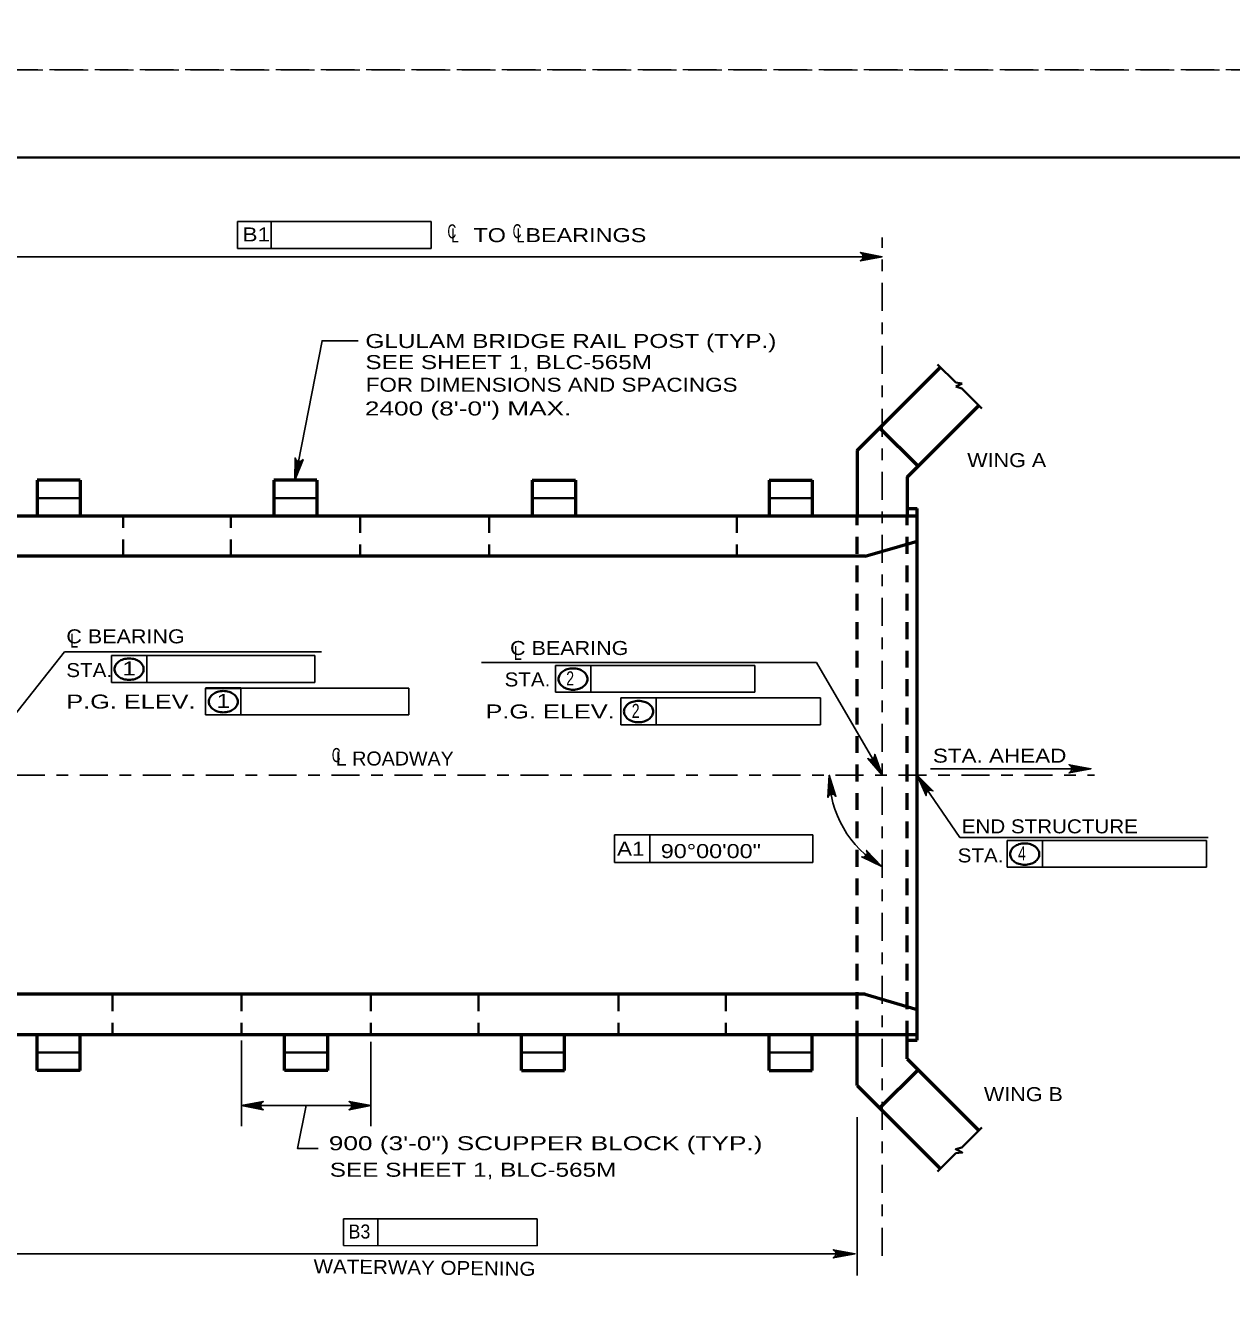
# Model space of a CAD drawing. Extents: x -11 to 79, y -154 to 0.
# Drawn here: x 5.96 to 16.3, y -32.54 to -21.62 of the extents above; entities that cross this region are included whole.
import ezdxf
from ezdxf.enums import TextEntityAlignment as Align

# ---------------------------------------------------------------- set-up
doc = ezdxf.new("R2010")
doc.units = 0
doc.header["$LTSCALE"] = 0.048
for name, pattern in [('DOT_DASHED', [7.7, 5, -1.2, 0.3, -1.2]), ('LONG_DASHED', [7.5, 6, -1.5]), ('MEDIUM_DASHED', [4.5, 3, -1.5])]:
    doc.linetypes.add(name, pattern=pattern)
for name, color, linetype, lineweight in [('1', 7, 'Continuous', 25), ('2', 7, 'Continuous', 35), ('3', 7, 'Continuous', 25), ('4', 7, 'Continuous', 25), ('63', 7, 'LONG_DASHED', 13)]:
    doc.layers.add(name, color=color, linetype=linetype, lineweight=lineweight)

msp = doc.modelspace()

# ---------------------------------------------------------------- hatches: boundary and pattern name
at = {"layer": '4'}
for points in [[(7.929, -30.85975), (7.929, -30.89917), (7.81083, -30.8795)], [(8.80092, -30.85975), (8.80092, -30.89917), (8.91908, -30.8795)]]:
    msp.add_hatch(color=256, dxfattribs=at).paths.add_polyline_path(points)

# ---------------------------------------------------------------- linework, layer by layer
at = {"layer": '1', "lineweight": 35}
msp.add_lwpolyline([(1.75, -43.25), (33.25, -43.25), (33.25, -22.75), (1.75, -22.75)], close=True, dxfattribs=at)
at = {"layer": '2', "lineweight": 53}
for p, q in [((13.08867, -25.26242), (13.80325, -24.54783)), ((13.61158, -25.398), (14.1325, -24.87708)), ((13.08867, -25.26242), (13.08867, -25.82425)), ((6.42675, -25.51667), (6.05767, -25.51667)), ((6.05767, -25.51667), (6.05767, -25.82425)), ((6.42675, -25.51667), (6.42675, -25.82425)), ((8.45675, -25.51667), (8.08767, -25.51667)), ((8.08767, -25.51667), (8.08767, -25.82425)), ((8.45675, -25.51667), (8.45675, -25.82425)), ((10.304, -25.51667), (10.67308, -25.51667)), ((10.304, -25.51667), (10.304, -25.82425)), ((10.67308, -25.51667), (10.67308, -25.82425)), ((12.334, -25.51667), (12.70308, -25.51667)), ((12.334, -25.51667), (12.334, -25.82425)), ((12.70308, -25.51667), (12.70308, -25.82425)), ((13.51925, -25.49025), (13.51925, -25.82425)), ((13.51925, -25.76017), (13.60442, -25.76017)), ((13.60442, -30.31925), (13.60442, -25.76017)), ((5.15625, -25.82425), (13.60442, -25.82425)), ((13.15733, -26.17025), (13.60442, -26.0395)), ((13.15733, -26.17025), (5.60342, -26.17025)), ((13.15733, -29.92517), (5.60342, -29.92517)), ((13.15733, -29.92517), (13.60442, -30.05583)), ((5.15625, -30.27117), (13.60442, -30.27117)), ((6.05767, -30.57875), (6.05767, -30.27117)), ((6.42675, -30.57875), (6.42675, -30.27117)), ((8.18033, -30.57875), (8.18033, -30.27117)), ((8.5495, -30.57875), (8.5495, -30.27117)), ((10.21125, -30.57875), (10.21125, -30.27117)), ((10.58033, -30.57875), (10.58033, -30.27117)), ((12.334, -30.57875), (12.334, -30.27117)), ((12.70308, -30.57875), (12.70308, -30.27117)), ((13.08867, -30.70708), (13.08867, -30.29592)), ((13.51925, -30.47917), (13.51925, -30.29592)), ((13.51925, -30.31925), (13.60442, -30.31925)), ((6.42675, -30.57875), (6.05767, -30.57875)), ((8.5495, -30.57875), (8.18033, -30.57875)), ((10.21125, -30.57875), (10.58033, -30.57875)), ((12.334, -30.57875), (12.70308, -30.57875)), ((13.61158, -30.5715), (13.28233, -30.90067)), ((13.51925, -30.47917), (14.1325, -31.09242)), ((13.08867, -30.70708), (13.80325, -31.42167))]:
    msp.add_line(p, q, dxfattribs=at)
at = {"layer": '2', "linetype": 'MEDIUM_DASHED', "lineweight": 53}
for p, q in [((13.08867, -30.29592), (13.08867, -25.82425)), ((13.51925, -30.29592), (13.51925, -25.82425))]:
    msp.add_line(p, q, dxfattribs=at)
at = {"layer": '2', "lineweight": 53}
msp.add_lwpolyline([(13.51925, -25.49025), (13.61158, -25.398), (13.28233, -25.06875)], dxfattribs=at)
at = {"layer": '3', "linetype": 'DOT_DASHED'}
msp.add_line((13.304, -32.16667), (13.304, -23.43658), dxfattribs=at)
at = {"layer": '3', "lineweight": 35}
for p, q in [((13.93633, -24.68083), (13.78, -24.5245)), ((13.93633, -24.68083), (13.99058, -24.68725)), ((13.99058, -24.68725), (13.93475, -24.71517)), ((13.93475, -24.71517), (13.98717, -24.73167)), ((14.158, -24.9025), (13.98717, -24.73167)), ((6.42675, -25.67042), (6.05767, -25.67042)), ((8.45675, -25.67042), (8.08767, -25.67042)), ((10.304, -25.67042), (10.67308, -25.67042)), ((12.334, -25.67042), (12.70308, -25.67042)), ((6.42675, -30.425), (6.05767, -30.425)), ((8.5495, -30.425), (8.18033, -30.425)), ((10.21125, -30.425), (10.58033, -30.425)), ((12.334, -30.425), (12.70308, -30.425)), ((14.158, -31.06692), (13.98717, -31.23775)), ((13.93633, -31.28858), (13.78, -31.44492))]:
    msp.add_line(p, q, dxfattribs=at)
at = {"layer": '3', "linetype": 'MEDIUM_DASHED', "lineweight": 35}
for p, q in [((6.79583, -26.17025), (6.79583, -25.82425)), ((7.71858, -26.17025), (7.71858, -25.82425)), ((8.82675, -25.82425), (8.82675, -26.15408)), ((9.934, -25.82425), (9.934, -26.17025)), ((12.05717, -25.82425), (12.05717, -26.17025)), ((6.70358, -29.92517), (6.70358, -30.27117)), ((7.81083, -29.92517), (7.81083, -30.27117)), ((8.919, -29.92517), (8.919, -30.27117)), ((9.84175, -29.92517), (9.84175, -30.27117)), ((11.04217, -29.92517), (11.04217, -30.27117)), ((11.96492, -29.92517), (11.96492, -30.27117))]:
    msp.add_line(p, q, dxfattribs=at)
at = {"layer": '3', "lineweight": 35}
msp.add_lwpolyline([(13.93633, -31.28858), (13.99058, -31.28217), (13.93475, -31.25425), (13.98717, -31.23775)], dxfattribs=at)
at = {"layer": '4'}
for p, q in [((7.77683, -23.30075), (8.066, -23.30075)), ((7.77683, -23.53142), (7.77683, -23.30075)), ((8.066, -23.53142), (8.066, -23.30075)), ((8.066, -23.30075), (9.43775, -23.30075)), ((9.43775, -23.30075), (9.43775, -23.53142)), ((9.43775, -23.53142), (7.77683, -23.53142)), ((5.45675, -23.60108), (13.304, -23.60108)), ((5.45675, -28.04325), (6.29333, -26.98983)), ((8.49633, -26.98983), (6.29333, -26.98983)), ((6.69533, -27.02042), (6.9985, -27.02042)), ((6.69533, -27.25117), (6.69533, -27.02042)), ((6.9985, -27.25117), (6.9985, -27.02042)), ((6.9985, -27.02042), (8.43875, -27.02042)), ((8.43875, -27.02042), (8.43875, -27.25117)), ((12.74142, -27.0805), (9.86892, -27.0805)), ((13.304, -28.04767), (12.74142, -27.0805)), ((10.502, -27.10525), (10.80508, -27.10525)), ((10.502, -27.33592), (10.502, -27.10525)), ((10.80508, -27.33592), (10.80508, -27.10525)), ((10.80508, -27.10525), (12.21242, -27.10525)), ((12.21242, -27.10525), (12.21242, -27.33592)), ((6.69533, -27.25117), (8.43875, -27.25117)), ((7.50292, -27.52983), (7.50292, -27.29917)), ((7.80608, -27.52983), (7.80608, -27.29917)), ((7.80608, -27.29917), (9.24633, -27.29917)), ((9.24633, -27.29917), (9.24633, -27.52983)), ((10.502, -27.33592), (12.21242, -27.33592)), ((11.06367, -27.38392), (11.36675, -27.38392)), ((11.06367, -27.61458), (11.06367, -27.38392)), ((11.36675, -27.61458), (11.36675, -27.38392)), ((11.36675, -27.38392), (12.77408, -27.38392)), ((12.77408, -27.38392), (12.77408, -27.61458)), ((7.50292, -27.52983), (9.24633, -27.52983)), ((11.06367, -27.61458), (12.77408, -27.61458)), ((13.60442, -28.04767), (13.97142, -28.58125)), ((15.0935, -27.9915), (13.71917, -27.9915)), ((11.00908, -28.559), (11.00883, -28.79517)), ((11.00908, -28.559), (11.31158, -28.559)), ((11.31133, -28.79517), (11.31158, -28.559)), ((11.31158, -28.559), (12.70992, -28.559)), ((12.70967, -28.79517), (12.70992, -28.559)), ((13.97142, -28.58125), (16.09875, -28.58125)), ((14.37533, -28.60592), (14.6785, -28.60592)), ((14.37533, -28.83658), (14.37533, -28.60592)), ((14.6785, -28.83658), (14.6785, -28.60592)), ((14.6785, -28.60592), (16.08575, -28.60592)), ((16.08575, -28.60592), (16.08575, -28.83658)), ((11.00883, -28.79517), (12.70967, -28.79517)), ((14.37533, -28.83658), (16.08575, -28.83658)), ((7.81083, -30.32133), (7.81083, -31.05667)), ((8.91908, -30.33258), (8.91908, -31.05667)), ((7.81083, -30.8795), (8.91908, -30.8795)), ((13.08867, -30.97933), (13.08867, -32.336)), ((8.68575, -32.07983), (8.68592, -31.84917)), ((8.68592, -31.84917), (8.97983, -31.84925)), ((8.97975, -32.07992), (8.97983, -31.84925)), ((8.97983, -31.84925), (10.34675, -31.84992)), ((10.34675, -31.84992), (10.34667, -32.08075)), ((10.34667, -32.08075), (8.68575, -32.07983)), ((5.67208, -32.14992), (13.07158, -32.14992))]:
    msp.add_line(p, q, dxfattribs=at)
at = {"layer": '4', "lineweight": 35}
msp.add_line((7.50292, -27.29917), (7.80608, -27.29917), dxfattribs=at)
at = {"layer": '4', "linetype": 'DOT_DASHED'}
msp.add_line((3.72342, -28.04767), (15.124, -28.04767), dxfattribs=at)
at = {"layer": '4'}
for points in [[(13.304, -23.60108), (13.11758, -23.636), (13.13192, -23.62608), (13.13933, -23.61358), (13.1415, -23.60108), (13.13933, -23.58858), (13.13192, -23.57608), (13.11758, -23.56617), (13.304, -23.60108), (13.13192, -23.57608), (13.13933, -23.58858), (13.304, -23.60108), (13.1415, -23.60108), (13.13933, -23.61358), (13.304, -23.60108), (13.13192, -23.62608)], [(8.26875, -25.51667), (8.50217, -24.32208), (8.81108, -24.32208)], [(8.26875, -25.51667), (8.27017, -25.327), (8.27717, -25.343), (8.28808, -25.35267), (8.29992, -25.35717), (8.31258, -25.3575), (8.32625, -25.35258), (8.33883, -25.34042), (8.26875, -25.51667), (8.32625, -25.35258), (8.31258, -25.3575), (8.26875, -25.51667), (8.29992, -25.35717), (8.28808, -25.35267), (8.26875, -25.51667), (8.27717, -25.343)], [(13.304, -28.04767), (13.18008, -27.90408), (13.19592, -27.9115), (13.21042, -27.91167), (13.22233, -27.90717), (13.232, -27.89908), (13.23908, -27.88642), (13.2405, -27.86892), (13.304, -28.04767), (13.23908, -27.88642), (13.232, -27.89908), (13.304, -28.04767), (13.22233, -27.90717), (13.21042, -27.91167), (13.304, -28.04767), (13.19592, -27.9115)], [(15.0935, -27.9915), (14.90708, -28.02642), (14.92142, -28.0165), (14.92883, -28.004), (14.931, -27.9915), (14.92883, -27.979), (14.92142, -27.9665), (14.90708, -27.95658), (15.0935, -27.9915), (14.92142, -27.9665), (14.92883, -27.979), (15.0935, -27.9915), (14.931, -27.9915), (14.92883, -28.004), (15.0935, -27.9915), (14.92142, -28.0165)], [(12.85067, -28.04767), (12.90792, -28.2285), (12.89633, -28.21542), (12.883, -28.20958), (12.87033, -28.209), (12.85817, -28.21267), (12.84667, -28.2215), (12.8385, -28.23692), (12.85067, -28.04767), (12.84667, -28.2215), (12.85817, -28.21267), (12.85067, -28.04767), (12.87033, -28.209), (12.883, -28.20958), (12.85067, -28.04767), (12.89633, -28.21542)], [(13.60442, -28.04767), (13.73883, -28.18142), (13.7225, -28.17525), (13.708, -28.17625), (13.6965, -28.18158), (13.68742, -28.19042), (13.68133, -28.20358), (13.68125, -28.22108), (13.60442, -28.04767), (13.68133, -28.20358), (13.68742, -28.19042), (13.60442, -28.04767), (13.6965, -28.18158), (13.708, -28.17625), (13.60442, -28.04767), (13.7225, -28.17525)], [(13.30133, -28.82833), (13.12967, -28.74775), (13.14708, -28.74808), (13.16042, -28.74225), (13.16958, -28.73333), (13.17508, -28.72192), (13.17633, -28.7075), (13.17058, -28.691), (13.30133, -28.82833), (13.17633, -28.7075), (13.17508, -28.72192), (13.30133, -28.82833), (13.16958, -28.73333), (13.16042, -28.74225), (13.30133, -28.82833), (13.14708, -28.74808)], [(7.81083, -30.8795), (7.99725, -30.84458), (7.98292, -30.8545), (7.9755, -30.867), (7.97333, -30.8795), (7.9755, -30.892), (7.98292, -30.9045), (7.99725, -30.91442), (7.81083, -30.8795), (7.98292, -30.9045), (7.9755, -30.892), (7.81083, -30.8795), (7.97333, -30.8795), (7.9755, -30.867), (7.81083, -30.8795), (7.98292, -30.8545)], [(8.36492, -30.8795), (8.29108, -31.2485), (8.46817, -31.2485)], [(8.91908, -30.8795), (8.73267, -30.91442), (8.747, -30.9045), (8.75442, -30.892), (8.75658, -30.8795), (8.75442, -30.867), (8.747, -30.8545), (8.73267, -30.84458), (8.91908, -30.8795), (8.747, -30.8545), (8.75442, -30.867), (8.91908, -30.8795), (8.75658, -30.8795), (8.75442, -30.892), (8.91908, -30.8795), (8.747, -30.9045)], [(13.07158, -32.14983), (12.88517, -32.18483), (12.89958, -32.17483), (12.907, -32.16233), (12.90908, -32.14983), (12.907, -32.13733), (12.89958, -32.12483), (12.88517, -32.11492), (13.07158, -32.14983), (12.89958, -32.12483), (12.907, -32.13733), (13.07158, -32.14983), (12.90908, -32.14983), (12.907, -32.16233), (13.07158, -32.14983), (12.89958, -32.17483)]]:
    msp.add_lwpolyline(points, dxfattribs=at)
for points in [[(7.929, -30.85975), (7.929, -30.89917), (7.81083, -30.8795)], [(8.80092, -30.85975), (8.80092, -30.89917), (8.91908, -30.8795)]]:
    msp.add_lwpolyline(points, close=True, dxfattribs=at)
at = {"layer": '4', "lineweight": 35}
for centre, radius, start, end in [((6.81749, -27.15288), 0.09948, 126.35438, 150.63079), ((6.83516, -27.17688), 0.12928, 106.95519, 126.35438), ((6.8467, -27.21473), 0.16885, 90, 106.95519), ((6.8467, -27.21473), 0.16885, 73.04481, 90), ((6.85824, -27.17688), 0.12928, 53.64563, 73.04481), ((6.8759, -27.15288), 0.09948, 29.36921, 53.64562), ((6.79045, -27.13766), 0.06845, 150.63079, 180), ((6.79045, -27.13766), 0.06845, 180, 209.36921), ((6.81749, -27.12244), 0.09948, 209.36921, 233.64562), ((6.8759, -27.12244), 0.09948, 306.35438, 330.63079), ((6.90295, -27.13766), 0.06845, 0, 29.36921), ((6.90295, -27.13766), 0.06845, 330.63079, 0), ((10.59708, -27.22244), 0.06845, 150.63079, 180), ((10.62412, -27.23766), 0.09948, 126.35438, 150.63079), ((10.64179, -27.26166), 0.12928, 106.95519, 126.35438), ((10.65333, -27.29951), 0.16885, 90, 106.95519), ((10.65333, -27.29951), 0.16885, 73.04481, 90), ((10.66487, -27.26166), 0.12928, 53.64563, 73.04481), ((10.68253, -27.23766), 0.09948, 29.36921, 53.64562), ((10.70958, -27.22244), 0.06845, 0, 29.36921), ((6.83516, -27.09844), 0.12928, 233.64562, 253.04481), ((6.8467, -27.06059), 0.16885, 253.04481, 270), ((6.8467, -27.06059), 0.16885, 270, 286.95519), ((6.85824, -27.09844), 0.12928, 286.95519, 306.35438), ((10.59708, -27.22244), 0.06845, 180, 209.36921), ((10.62412, -27.20722), 0.09948, 209.36921, 233.64562), ((10.64179, -27.18322), 0.12928, 233.64562, 253.04481), ((10.65333, -27.14537), 0.16885, 253.04481, 270), ((10.65333, -27.14537), 0.16885, 270, 286.95519), ((10.66487, -27.18322), 0.12928, 286.95519, 306.35438), ((10.68253, -27.20722), 0.09948, 306.35438, 330.63079), ((10.70958, -27.22244), 0.06845, 330.63079, 0), ((7.59801, -27.41635), 0.06845, 150.63079, 180), ((7.59801, -27.41635), 0.06845, 180, 209.36921), ((7.62506, -27.43157), 0.09948, 126.35438, 150.63079), ((7.64272, -27.45557), 0.12928, 106.95519, 126.35438), ((7.65426, -27.49343), 0.16885, 90, 106.95519), ((7.65426, -27.49343), 0.16885, 73.04481, 90), ((7.6658, -27.45557), 0.12928, 53.64563, 73.04481), ((7.68347, -27.43157), 0.09948, 29.36921, 53.64562), ((7.71051, -27.41635), 0.06845, 0, 29.36921), ((7.71051, -27.41635), 0.06845, 330.63079, 0), ((11.21498, -27.5782), 0.16885, 90, 106.95519), ((11.21498, -27.5782), 0.16885, 73.04481, 90), ((7.62506, -27.40113), 0.09948, 209.36921, 233.64562), ((7.64272, -27.37714), 0.12928, 233.64562, 253.04481), ((7.65426, -27.33928), 0.16885, 253.04481, 270), ((7.65426, -27.33928), 0.16885, 270, 286.95519), ((7.6658, -27.37714), 0.12928, 286.95519, 306.35438), ((7.68347, -27.40113), 0.09948, 306.35438, 330.63079), ((11.15873, -27.50113), 0.06845, 150.63079, 180), ((11.15873, -27.50113), 0.06845, 180, 209.36921), ((11.18577, -27.51635), 0.09948, 126.35438, 150.63079), ((11.20344, -27.54035), 0.12928, 106.95519, 126.35438), ((11.22652, -27.54035), 0.12928, 53.64563, 73.04481), ((11.24418, -27.51635), 0.09948, 29.36921, 53.64562), ((11.27123, -27.50113), 0.06845, 0, 29.36921), ((11.27123, -27.50113), 0.06845, 330.63079, 0), ((11.18577, -27.48591), 0.09948, 209.36921, 233.64562), ((11.20344, -27.46191), 0.12928, 233.64562, 253.04481), ((11.21498, -27.42406), 0.16885, 253.04481, 270), ((11.21498, -27.42406), 0.16885, 270, 286.95519), ((11.22652, -27.46191), 0.12928, 286.95519, 306.35438), ((11.24418, -27.48591), 0.09948, 306.35438, 330.63079), ((14.47042, -28.72315), 0.06845, 150.63079, 180), ((14.47042, -28.72315), 0.06845, 180, 209.36921), ((14.49746, -28.73838), 0.09948, 126.35438, 150.63079), ((14.51513, -28.76237), 0.12928, 106.95519, 126.35438), ((14.52667, -28.80023), 0.16885, 90, 106.95519), ((14.52667, -28.80023), 0.16885, 73.04481, 90), ((14.53821, -28.76237), 0.12928, 53.64563, 73.04481), ((14.55587, -28.73838), 0.09948, 29.36921, 53.64562), ((14.58292, -28.72315), 0.06845, 0, 29.36921), ((14.58292, -28.72315), 0.06845, 330.63079, 0), ((14.49746, -28.70793), 0.09948, 209.36921, 233.64562), ((14.51513, -28.68394), 0.12928, 233.64562, 253.04481), ((14.52667, -28.64608), 0.16885, 253.04481, 270), ((14.52667, -28.64608), 0.16885, 270, 286.95519), ((14.53821, -28.68394), 0.12928, 286.95519, 306.35438), ((14.55587, -28.70793), 0.09948, 306.35438, 330.63079)]:
    msp.add_arc(centre, radius, start, end, dxfattribs=at)
at = {"layer": '4'}
msp.add_arc((13.75206, -28.04769), 0.90143, 179.99929, 239.99945, dxfattribs=at)
at = {"layer": '63'}
for points in [[(0, -22), (34, -22), (34, 0), (0, 0)], [(0, -44), (34, -44), (34, -22), (0, -22)]]:
    msp.add_lwpolyline(points, close=True, dxfattribs=at)

# ---------------------------------------------------------------- texts
at = {"layer": '2'}
for s, width, p in [('C', 0.65, (9.57667, -23.44392)), ('L', 0.75, (9.608, -23.47942)), ('C', 0.65, (10.13575, -23.44267)), ('L', 0.75, (10.16883, -23.47942))]:
    msp.add_text(s, height=0.12, dxfattribs=dict(at, width=width)).set_placement(p)
at = {"layer": '4'}
for s, width, p in [('B1', 1.2, (7.81942, -23.47042)), ('TO   BEARINGS', 1.25, (9.79925, -23.4765)), ('GLULAM BRIDGE RAIL POST (TYP.)', 1.3, (8.87308, -24.38417)), ('SEE SHEET 1, BLC-565M', 1.3, (8.87308, -24.56508)), ('FOR DIMENSIONS AND SPACINGS', 1.2, (8.87558, -24.75917)), ('2400 (8\'-0") MAX.', 1.4, (8.86833, -24.96258)), ('WING A', 1.15, (14.03392, -25.40542)), ('C BEARING', 1.15, (6.30842, -26.91617)), ('L', 0.75, (6.34133, -26.95275)), ('C BEARING', 1.15, (10.11317, -27.01617)), ('L', 0.75, (10.14617, -27.05833)), ('STA.', 1.1, (6.30842, -27.20567)), ('1', 1.3, (6.78867, -27.19167)), ('STA.', 1.1, (10.06642, -27.286)), ('2', 0.75, (10.59525, -27.27642)), ('P.G. ELEV.', 1.35, (6.30842, -27.47567)), ('1', 1.3, (7.59617, -27.47033)), ('P.G. ELEV.', 1.35, (9.90275, -27.56042)), ('2', 0.75, (11.15692, -27.55517)), ('C', 0.65, (8.58492, -27.93383)), ('L ROADWAY', 1.05, (8.61933, -27.96358)), ('STA. AHEAD', 1.2, (13.739, -27.93925)), ('END STRUCTURE', 1.1, (13.9865, -28.54508)), ('90°00\'00"', 1.25, (11.4055, -28.75717)), ('STA.', 1.1, (13.95158, -28.79458)), ('4', 0.75, (14.46858, -28.77717)), ('WING B', 1.15, (14.17667, -30.84125)), ('900 (3\'-0") SCUPPER BLOCK (TYP.)', 1.4, (8.55933, -31.26217)), ('SEE SHEET 1, BLC-565M', 1.3, (8.56725, -31.48925))]:
    msp.add_text(s, height=0.12, dxfattribs=dict(at, width=width)).set_placement(p)
for s, rotation, width, p in [('A1', 359.938, 1.2, (11.1486, -28.73713)), ('WATERWAY OPENING', 359.308, 1.1, (9.37894, -32.32799))]:
    msp.add_text(s, height=0.12, rotation=rotation, dxfattribs=dict(at, width=width)).set_placement(p, align=Align.CENTER)
at = {"layer": '4', "width": 0.95}
msp.add_text('B3', height=0.12, rotation=359.969, dxfattribs=at).set_placement((8.7285, -32.01883))

doc.saveas('drawing.dxf')
